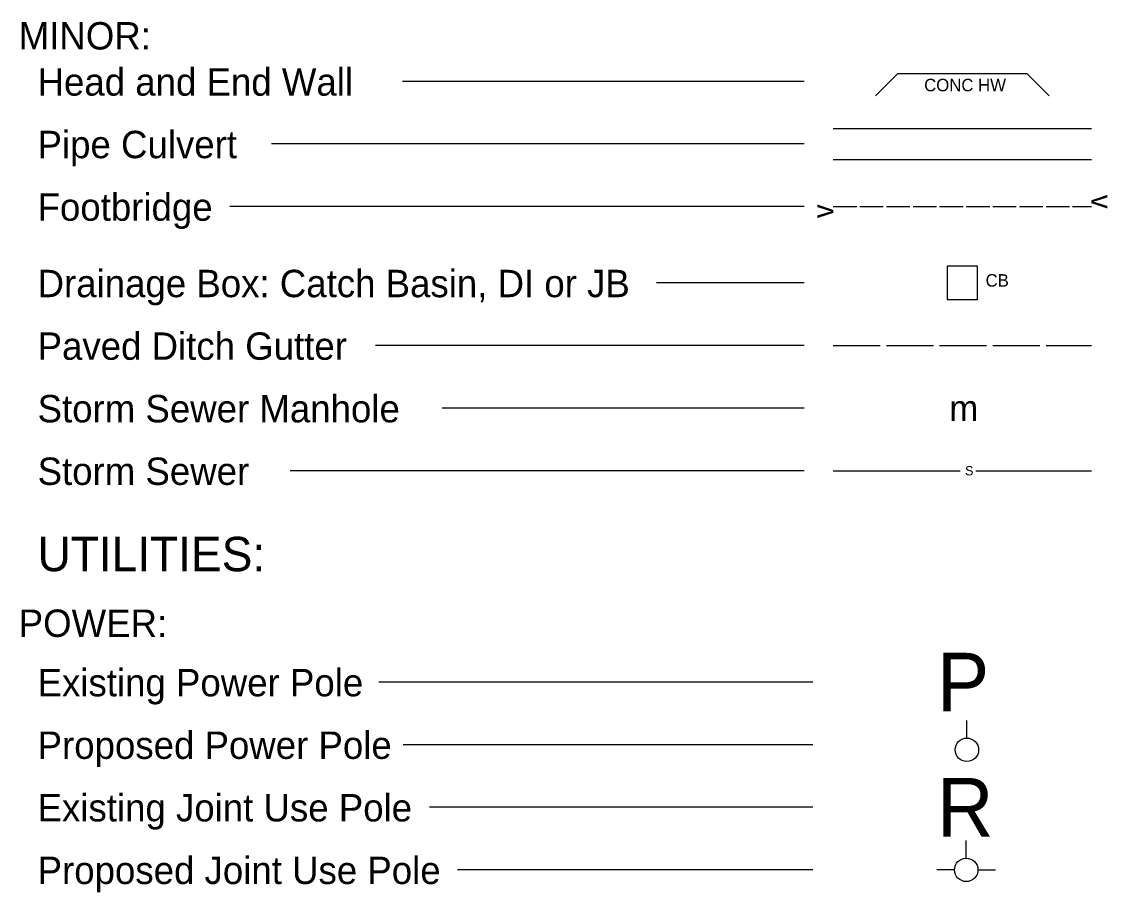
# Model space of a CAD drawing. Extents: x 1729989.5 to 1730023.2, y 539942.1 to 539964.1.
# Drawn here: x 1730008.13 to 1730015.07, y 539952.85 to 539958.41 of the extents above; entities that cross this region are included whole.
import ezdxf

# ---------------------------------------------------------------- set-up
doc = ezdxf.new("R2010")
doc.units = 0
doc.layers.add('Sheet Symbology CELL', color=7, linetype='Continuous')

msp = doc.modelspace()

# ---------------------------------------------------------------- linework, layer by layer
at = {"layer": 'Sheet Symbology CELL'}
for p, q in [((1730013.1308, 539958.0299), (1730010.5648, 539958.0299)), ((1730013.5878, 539957.9384), (1730013.7293, 539958.0799)), ((1730013.7293, 539958.0799), (1730014.5543, 539958.0799)), ((1730014.5543, 539958.0799), (1730014.6958, 539957.9384)), ((1730013.3168, 539957.7299), (1730014.9668, 539957.7299)), ((1730013.1308, 539957.6299), (1730009.727, 539957.6299)), ((1730013.3168, 539957.5299), (1730014.9668, 539957.5299)), ((1730013.1308, 539957.2299), (1730009.4613, 539957.2299)), ((1730013.3168, 539957.2299), (1730013.4668, 539957.2299)), ((1730013.4868, 539957.2299), (1730013.6368, 539957.2299)), ((1730013.6568, 539957.2299), (1730013.8068, 539957.2299)), ((1730013.8268, 539957.2299), (1730013.9768, 539957.2299)), ((1730013.9968, 539957.2299), (1730014.1468, 539957.2299)), ((1730014.1668, 539957.2299), (1730014.3168, 539957.2299)), ((1730014.3368, 539957.2299), (1730014.4868, 539957.2299)), ((1730014.5068, 539957.2299), (1730014.6568, 539957.2299)), ((1730014.6768, 539957.2299), (1730014.8268, 539957.2299)), ((1730014.8468, 539957.2299), (1730014.9668, 539957.2299)), ((1730013.1308, 539956.7413), (1730012.1868, 539956.7413)), ((1730013.1308, 539956.3413), (1730010.3918, 539956.3413)), ((1730013.3168, 539956.3413), (1730013.6168, 539956.3413)), ((1730013.6568, 539956.3413), (1730013.9568, 539956.3413)), ((1730013.9968, 539956.3413), (1730014.2968, 539956.3413)), ((1730014.3368, 539956.3413), (1730014.6368, 539956.3413)), ((1730014.6768, 539956.3413), (1730014.9668, 539956.3413)), ((1730013.1308, 539955.9413), (1730010.8173, 539955.9413)), ((1730013.1308, 539955.5413), (1730009.8468, 539955.5413)), ((1730013.3168, 539955.5413), (1730014.1273, 539955.5413)), ((1730014.2273, 539955.5413), (1730014.9668, 539955.5413)), ((1730013.1865, 539954.1895), (1730010.4125, 539954.1895)), ((1730014.171, 539953.8318), (1730014.171, 539953.9443)), ((1730013.1865, 539953.7895), (1730010.5683, 539953.7895)), ((1730013.1865, 539953.3895), (1730010.7363, 539953.3895)), ((1730014.1668, 539953.0648), (1730014.1668, 539953.1773)), ((1730013.1865, 539952.9895), (1730010.9163, 539952.9895)), ((1730014.0918, 539952.9898), (1730013.9793, 539952.9898)), ((1730014.2418, 539952.9898), (1730014.3543, 539952.9898))]:
    msp.add_line(p, q, dxfattribs=at)
msp.add_lwpolyline([(1730014.0455, 539956.635), (1730014.2378, 539956.635), (1730014.2378, 539956.8478), (1730014.0455, 539956.8478)], close=True, dxfattribs=at)
for centre in [(1730014.171, 539953.7568), (1730014.1668, 539952.9895)]:
    msp.add_circle(centre, 0.075, dxfattribs=at)

# ---------------------------------------------------------------- texts
for s, height, p in [('MINOR:', 0.175, (1730008.111, 539958.234)), ('Head and End Wall', 0.175001, (1730008.2315, 539957.9389)), ('Pipe Culvert', 0.175001, (1730008.2315, 539957.5391)), ('Footbridge', 0.175, (1730008.2318, 539957.1391)), ('Drainage Box: Catch Basin, DI or JB', 0.175001, (1730008.2318, 539956.6505)), ('Paved Ditch Gutter', 0.175001, (1730008.2318, 539956.2503)), ('Storm Sewer Manhole', 0.175001, (1730008.2318, 539955.8503)), ('m', 0.165, (1730014.0593, 539955.8588)), ('Storm Sewer', 0.175001, (1730008.2318, 539955.4503)), ('S', 0.06, (1730014.1593, 539955.5113)), ('UTILITIES:', 0.22, (1730008.2315, 539954.8985)), ('POWER:', 0.175, (1730008.111, 539954.4788)), ('P', 0.375, (1730013.9793, 539954.002)), ('Existing Power Pole', 0.175001, (1730008.2318, 539954.0988)), ('Proposed Power Pole', 0.175001, (1730008.2318, 539953.6988)), ('R', 0.375, (1730013.9793, 539953.202)), ('Existing Joint Use Pole', 0.175001, (1730008.2318, 539953.299)), ('Proposed Joint Use Pole', 0.175001, (1730008.232, 539952.8988))]:
    msp.add_text(s, height=height, dxfattribs=at).set_placement(p)
for s, height, rotation, p in [('CONC HW', 0.08, 360, (1730013.8978, 539957.9666)), ('v', 0.132, 270.24085, (1730014.9665, 539957.3046)), ('v', 0.132, 89.75915, (1730013.3165, 539957.1551)), ('CB', 0.08, 360, (1730014.2905, 539956.7178))]:
    msp.add_text(s, height=height, rotation=rotation, dxfattribs=at).set_placement(p)

doc.saveas('drawing.dxf')
